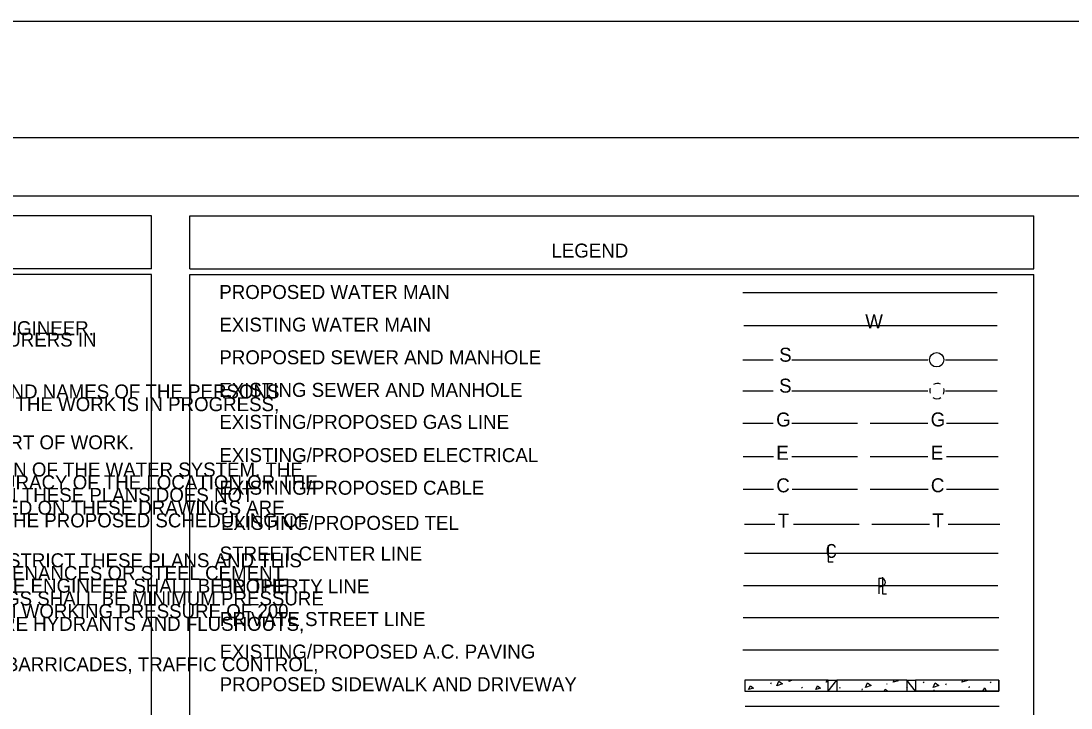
# Model space of a CAD drawing. Extents: x 837 to 1117, y 1316 to 1424.
# Drawn here: x 853.74 to 862.75, y 1416.35 to 1422.24 of the extents above; entities that cross this region are included whole.
import ezdxf

# ---------------------------------------------------------------- set-up
doc = ezdxf.new("R2010")
doc.units = 0
for name, color, linetype in [('0 (Construction)', 7, 'Continuous'), ('BASEMAP', 7, 'Continuous'), ('Existing AC Pavement', 7, 'Continuous'), ('Existing Sewer', 7, 'Continuous'), ('Existing Water', 7, 'Continuous'), ('LLINES', 7, 'Continuous'), ('lot lines', 7, 'Continuous'), ('Pvt and Future St', 7, 'Continuous'), ('Survey Control', 7, 'Continuous')]:
    doc.layers.add(name, color=color, linetype=linetype)

# ---------------------------------------------------------------- blocks, each defined once
blk = doc.blocks.new('ZPL_1')
at = {"layer": 'Existing Sewer'}
for p, q in [((0, 1213), (0, 0)), ((0, 0), (468, 0))]:
    blk.add_line(p, q, dxfattribs=at)
blk.add_text('C', height=1013, dxfattribs=at).set_placement((-208, 280))

msp = doc.modelspace()

# ---------------------------------------------------------------- linework, layer by layer
at = {"layer": '0 (Construction)'}
msp.add_lwpolyline([(841.77, 1422.24), (877.77, 1422.24), (877.77, 1398.24), (841.77, 1398.24)], close=True, dxfattribs=at)
at = {"layer": 'BASEMAP'}
for p, q in [((843.02, 1421.24), (877.02, 1421.24)), ((843.52, 1420.74), (876.52, 1420.74)), ((854.8567, 1420.5693), (843.6776, 1420.5693)), ((854.8567, 1420.1133), (854.8567, 1420.5693)), ((855.1881, 1420.5693), (862.4361, 1420.5693)), ((855.1881, 1420.1133), (855.1881, 1420.5693)), ((862.4361, 1420.1133), (862.4361, 1420.5693)), ((854.8567, 1420.1133), (843.6776, 1420.1133)), ((855.1881, 1420.1133), (862.4361, 1420.1133)), ((854.8567, 1420.0652), (843.6776, 1420.0653)), ((854.8567, 1399.867), (854.8567, 1420.0652)), ((855.1875, 1411.0955), (855.1881, 1420.0653)), ((855.1881, 1420.0653), (862.4361, 1420.0653)), ((862.4361, 1411.0955), (862.4361, 1420.0653))]:
    msp.add_line(p, q, dxfattribs=at)
at = {"layer": 'Existing AC Pavement'}
msp.add_line((862.1324, 1416.8412), (859.9354, 1416.8412), dxfattribs=at)
at = {"layer": 'Existing Sewer'}
for p, q in [((861.1042, 1417.4589), (861.1042, 1417.3235)), ((861.1042, 1417.4589), (861.1239, 1417.4589)), ((861.1343, 1417.4665), (861.1343, 1417.3235)), ((861.1042, 1417.3873), (861.1239, 1417.3873)), ((861.1343, 1417.3235), (861.1697, 1417.3235))]:
    msp.add_line(p, q, dxfattribs=at)
msp.add_circle((861.6007, 1419.333), 0.0617, dxfattribs=at)
msp.add_arc((861.1239, 1417.4231), 0.0358, 270, 90, dxfattribs=at)
at = {"layer": 'Existing Water'}
msp.add_line((859.9441, 1419.6279), (862.1212, 1419.6265), dxfattribs=at)
at = {"layer": 'LLINES'}
for p, q in [((859.9361, 1419.9098), (862.1209, 1419.9098)), ((859.9366, 1419.333), (860.1974, 1419.333)), ((860.3571, 1419.333), (860.9193, 1419.333)), ((860.9193, 1419.333), (861.5249, 1419.333)), ((861.6765, 1419.333), (862.1214, 1419.333)), ((859.9358, 1419.0675), (860.1966, 1419.0675)), ((860.3563, 1419.0675), (860.9185, 1419.0675)), ((860.9185, 1419.0675), (861.5241, 1419.0675)), ((861.6757, 1419.0675), (862.1206, 1419.0675)), ((859.9363, 1418.7878), (860.1971, 1418.7878)), ((860.3569, 1418.7878), (860.9191, 1418.7878)), ((861.0292, 1418.7878), (861.5246, 1418.7878)), ((861.6836, 1418.7882), (862.1285, 1418.7882)), ((859.9373, 1418.5028), (860.1981, 1418.5028)), ((860.3578, 1418.5028), (860.92, 1418.5028)), ((861.0301, 1418.5028), (861.5255, 1418.5028)), ((861.6845, 1418.5031), (862.1294, 1418.5031)), ((859.9378, 1418.2231), (860.1986, 1418.2231)), ((860.3583, 1418.2231), (860.9206, 1418.2231)), ((861.0306, 1418.2231), (861.5261, 1418.2231)), ((861.6851, 1418.2234), (862.13, 1418.2234)), ((859.9509, 1417.9212), (860.2117, 1417.9212)), ((860.3714, 1417.9212), (860.9336, 1417.9212)), ((861.0437, 1417.9212), (861.5391, 1417.9212)), ((861.6981, 1417.9216), (862.143, 1417.9216)), ((860.1771, 1416.553), (860.1822, 1416.5643)), ((860.3327, 1416.571), (860.3344, 1416.583)), ((860.4392, 1416.5224), (860.4444, 1416.5147)), ((860.6691, 1416.4892), (860.744, 1416.583)), ((860.6691, 1416.583), (860.744, 1416.583)), ((860.744, 1416.583), (860.744, 1416.4892)), ((861.3443, 1416.583), (860.744, 1416.583)), ((860.7649, 1416.5239), (860.77, 1416.5163)), ((860.9595, 1416.4989), (860.9646, 1416.5104)), ((861.1687, 1416.5565), (861.1738, 1416.5488)), ((861.3409, 1416.5239), (861.346, 1416.5163)), ((861.3443, 1416.583), (861.3443, 1416.4892)), ((861.4191, 1416.4892), (861.3443, 1416.583)), ((861.3443, 1416.583), (861.4191, 1416.583)), ((862.1347, 1416.583), (861.4191, 1416.583)), ((861.484, 1416.5698), (861.4891, 1416.5621)), ((861.6786, 1416.5448), (861.6837, 1416.5563)), ((861.8781, 1416.5181), (861.8832, 1416.5296)), ((862.06, 1416.5698), (862.0651, 1416.5621)), ((862.1347, 1416.583), (862.1347, 1416.4892)), ((860.6691, 1416.4892), (860.744, 1416.4892)), ((860.744, 1416.4892), (861.3443, 1416.4892)), ((861.3443, 1416.4892), (861.4191, 1416.4892)), ((862.1347, 1416.4892), (861.4191, 1416.4892)), ((861.575, 1416.4887), (861.5801, 1416.5002)), ((859.9546, 1416.3594), (862.1357, 1416.3594))]:
    msp.add_line(p, q, dxfattribs=at)
for points in [[(860.6691, 1416.583), (859.9536, 1416.583), (859.9536, 1416.4892), (860.6691, 1416.4892), (860.6691, 1416.583)], [(859.9853, 1416.5024), (860.0007, 1416.5344), (860.0263, 1416.5152), (859.9853, 1416.5024)], [(860.2274, 1416.5358), (860.2459, 1416.5742), (860.2766, 1416.5512), (860.2274, 1416.5358)], [(860.3589, 1416.583), (860.3339, 1416.5715)], [(860.5613, 1416.5024), (860.5767, 1416.5344), (860.6023, 1416.5152), (860.5613, 1416.5024)], [(860.6513, 1416.5654), (860.6598, 1416.583)], [(860.6691, 1416.5709), (860.6513, 1416.5654)], [(860.9889, 1416.5218), (861.0074, 1416.5602), (861.0381, 1416.5372), (860.9889, 1416.5218)], [(861.2273, 1416.5654), (861.2358, 1416.583)], [(861.2618, 1416.583), (861.2683, 1416.5782), (861.2273, 1416.5654)], [(862.1347, 1416.583), (861.4191, 1416.583), (861.4191, 1416.4892), (862.1347, 1416.4892), (862.1347, 1416.583)], [(861.5698, 1416.5218), (861.5883, 1416.5602), (861.6189, 1416.5372), (861.5698, 1416.5218)], [(861.817, 1416.5653), (861.8255, 1416.583)], [(861.8629, 1416.583), (861.8661, 1416.5807), (861.817, 1416.5653)], [(861.9969, 1416.4892), (862.0129, 1416.5194), (862.0264, 1416.4892)], [(861.1503, 1416.4892), (861.1584, 1416.5061), (861.181, 1416.4892)]]:
    msp.add_lwpolyline(points, dxfattribs=at)
for centre, start, end in [((861.6074, 1419.0679), 66.04973, 122.83521), ((861.6031, 1419.0645), 157.92733, 196.20529), ((861.6031, 1419.0645), 334.89907, 21.4144), ((861.6036, 1419.06), 235.65003, 303.26702)]:
    msp.add_arc(centre, 0.0617, start, end, dxfattribs=at)
at = {"layer": 'lot lines'}
msp.add_line((859.9402, 1417.3962), (862.125, 1417.3962), dxfattribs=at)
at = {"layer": 'Pvt and Future St'}
msp.add_line((862.1343, 1417.1201), (859.9373, 1417.1201), dxfattribs=at)
at = {"layer": 'Survey Control'}
msp.add_line((859.9509, 1417.6747), (862.1279, 1417.6733), dxfattribs=at)

# ---------------------------------------------------------------- block references
at = {"layer": 'Existing Sewer', "xscale": 9.437072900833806e-05, "yscale": 0.00011796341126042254, "rotation": 6.72683340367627e-10}
msp.add_blockref('ZPL_1', (860.668, 1417.5995), dxfattribs=at)

# ---------------------------------------------------------------- texts
at = {"layer": 'Existing Sewer'}
msp.add_text('T', height=0.12, dxfattribs=at).set_placement((860.2365, 1417.8937))
at = {"layer": 'LLINES'}
for s, p in [('LEGEND', (858.2926, 1420.2101)), ('PROPOSED WATER MAIN', (855.44, 1419.8546)), ('         THE ENGINEER AND POSSESS A RETURNED COPY OF SUCH MARKED "APPROVED" FOR THIS PROJECT BY THE ENGINEER.', (844.2898, 1419.5441)), ('EXISTING WATER MAIN ', (855.4404, 1419.5746)), ('W ', (860.9872, 1419.6035)), ("     B)  HAVE SUBMITTED TO THE ENGINEER PROOF THAT THE AGENCY IS NAMED INSURED BY THE CONTRACTOR'S INSURERS IN ", (844.2181, 1419.4462)), ('PROPOSED SEWER AND MANHOLE', (855.4405, 1419.2944)), ('S  ', (860.2479, 1419.3165)), ('     C)  HAVE GIVEN THE ENGINEER THE TELEPHONE NUMBER, BUSINESS OR HOME ADDRESS AND MAILING ADDRESS AND NAMES OF THE PERSONS', (844.2227, 1419.0012)), ('EXISTING SEWER AND MANHOLE ', (855.4397, 1419.0148)), ('S  ', (860.2471, 1419.051)), ('         WHO CAN BE CONTACTED IN THE EVENT OF AN EMERGENCY OCCURRENCE ON THE PROJECT DURING THE TIME THE WORK IS IN PROGRESS,', (844.2931, 1418.8921)), ('EXISTING/PROPOSED GAS LINE', (855.4403, 1418.7399)), ('G', (860.2219, 1418.7603)), ('G', (861.5489, 1418.7611)), ('     D)  HAVE GIVEN THE ENGINEER 2 DAYS IN ADVANCE OF START OF WORK, NOTICE, IN WRITING, OF THE TIME OF START OF WORK.', (844.2227, 1418.5648)), ('EXISTING/PROPOSED ELECTRICAL', (855.4412, 1418.4549)), ('E', (860.2229, 1418.4753)), ('E', (861.5498, 1418.476)), ('IT IS RECOMMENDED THAT THE DEVELOPER CHECK THIS PLAN WITH HIS PLANS BEFORE COMMENCING CONSTRUCTION OF THE WATER SYSTEM. THE', (844.2195, 1418.3314)), ("WATER DISTRIBUTION SYSTEM PLAN FOR THIS PROJECT WAS PREPARED BY THE DEVELOPER'S ENGINEER.  THE ACCURACY OF THE LOCATION OR THE", (844.2181, 1418.2223)), ('C', (860.2234, 1418.1956)), ('C', (861.5503, 1418.1964)), ('EXISTENCE OR NONEXISTENCE OF ANY UTILITY PIPE OR STRUCTURE WITHIN THE LIMITS OF THIS PROJECT SHOWN ON THESE PLANS DOES NOT', (844.2229, 1418.1132)), ('EXISTING/PROPOSED CABLE', (855.4418, 1418.1752)), ('CONSTITUTE A GUARANTEE AS TO THEIR LOCATION BY THE AGENCY.  NEW PAVING, CURBS, AND SIDEWALKS INDICATED ON THESE DRAWINGS ARE', (844.2235, 1418.0041)), ('SHOWN FOR INFORMATION ONLY.  THE CONTRACTOR FOR THE WATER SYSTEM SHOULD VERIFY THE LOCATION AND THE PROPOSED SCHEDULING OF', (844.2195, 1417.895)), ('EXISTING/PROPOSED TEL', (855.4548, 1417.8733)), ('T', (861.5634, 1417.8945)), ('STREET CENTER LINE ', (855.4432, 1417.6104)), ('ALL WATER SYSTEM MATERIALS AND CONSTRUCTION METHODS SHALL COMPLY WITH THE REQUIREMENTS OF THE DISTRICT THESE PLANS AND THIS', (844.2195, 1417.5524)), ('LIST OF MATERIALS HAVE BEEN DETAILED FOR USE OF DUCTILE IRON, CEMENT MORTAR LINED FITTINGS AND APPURTENANCES OR STEEL CEMENT', (844.2268, 1417.4433)), ("MORTAR LINED AND COATED APPURTENANCES AS SHOWN.  THE CONTRACTOR'S MATERIAL LISTING APPROVED BY THE ENGINEER SHALL BE IN THE", (844.231, 1417.3342)), ('PROPERTY LINE ', (855.4442, 1417.3293)), ("CONTRACTOR'S POSSESSION PRIOR TO HIS PURCHASE OR FABRICATION OF SUCH MATERIALS.  DUCTILE IRON FITTINGS SHALL BE MINIMUM PRESSURE", (844.226, 1417.2253)), ('RATED 350 P.S.I., STEEL FITTINGS SHALL BE MINIMUM SCHEDULE 40.  ALL VALVES SHALL BE DESIGNED FOR A MINIMUM WORKING PRESSURE OF 200', (844.2288, 1417.1162)), ('PRIVATE STREET LINE', (855.4451, 1417.0481)), ('P.S.I.  CONTRACTOR SHALL APPLY TWO COATS OF HEAVY DUTY RED PRIMER AND TWO FINISH COATS OF PAINT TO FIRE HYDRANTS AND FLUSHOUTS,', (844.231, 1417.0071)), ('EXISTING/PROPOSED A.C. PAVING ', (855.4432, 1416.7692)), ('ALL WORK IS SUBJECT TO THE REQUIREMENTS OF THE PERMIT(S) OF THE CITY/COUNTY OF                        REGARDING BARRICADES, TRAFFIC CONTROL,', (844.2195, 1416.6599)), ('PROPOSED SIDEWALK AND DRIVEWAY', (855.4431, 1416.4889))]:
    msp.add_text(s, height=0.12, dxfattribs=at).set_placement(p)

doc.saveas('drawing.dxf')
